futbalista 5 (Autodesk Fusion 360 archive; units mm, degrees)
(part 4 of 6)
sketch "Sketch44" plane through (-7.5563, 42.8538, 0) normal (0.1736, -0.9848, 0) x axis (0.9848, 0.1736, 0)
  line L1 (43.4001, 36.25) -> (43.5001, 36.25)
  line L2 (43.4001, 23.75) -> (43.4001, 36.25)
  line L3 (43.5001, 23.75) -> (43.4001, 23.75)
  line L4 (43.5001, 23.4) -> (43.5001, 23.75)
  line L5 (58.7001, 23.4) -> (43.5001, 23.4)
  line L6 (58.7001, 36.6) -> (58.7001, 23.4)
  line L7 (43.5001, 36.6) -> (58.7001, 36.6)
  line L8 (43.5001, 36.25) -> (43.5001, 36.6)
  line L9 (58.7501, 34.41) -> (58.7501, 35.2)
  line L10 (58.7501, 24.8) -> (58.7501, 25.59)
  line L11 (51.6001, 22.55) -> (49.2001, 22.55)
  line L12 (51.6001, 37.45) -> (49.2001, 37.45)
  line L13 (42.8801, 30.05) -> (42.8801, 32.75)
  line L14 (42.8801, 29.95) -> (42.8801, 27.25)
  line L15 (42.4001, 17.25) -> (42.4001, 6.75)
  line L16 (44.2601, 4.75) -> (47.6601, 4.75)
  line L17 (52.7601, 4.75) -> (56.1601, 4.75)
  line L18 (47.6601, 19.25) -> (44.2601, 19.25)
  line L19 (56.1601, 19.25) -> (52.7601, 19.25)
  line L20 (58.0201, 12.01) -> (58.0201, 17.25)
  line L21 (58.0201, 6.75) -> (58.0201, 11.99)
  line L22 (45.1001, -14.5) -> (45.1001, 1)
  line L23 (45.3001, 1.2) -> (58.4001, 1.2)
  line L24 (58.6001, -4.12) -> (58.6001, -9.18)
  line L25 (58.4001, -14.7) -> (45.3001, -14.7)
  line L26 (45.1001, -14.7) -> (45.3001, -14.7)
  line L27 (45.1001, -14.5) -> (45.1001, -14.7)
  line L28 (58.6001, -14.7) -> (58.4001, -14.7)
  line L29 (58.6001, -9.18) -> (58.6001, -14.7)
  line L30 (58.6001, 1.2) -> (58.6001, -4.12)
  line L31 (58.4001, 1.2) -> (58.6001, 1.2)
  line L32 (45.1001, 1.2) -> (45.3001, 1.2)
  line L33 (45.1001, 1) -> (45.1001, 1.2)
  line L34 (58.0201, 4.75) -> (56.1601, 4.75)
  line L35 (58.0201, 6.75) -> (58.0201, 4.75)
  line L36 (47.6601, 4.75) -> (52.7601, 4.75)
  line L37 (42.4001, 4.75) -> (44.2601, 4.75)
  line L38 (42.4001, 6.75) -> (42.4001, 4.75)
  line L39 (42.4001, 19.25) -> (42.4001, 17.25)
  line L40 (44.2601, 19.25) -> (42.4001, 19.25)
  line L41 (52.7601, 19.25) -> (47.6601, 19.25)
  line L42 (58.0201, 19.25) -> (56.1601, 19.25)
  line L43 (58.0201, 17.25) -> (58.0201, 19.25)
  line L44 (58.0201, 11.99) -> (58.0201, 12.01)
  line L45 (58.7501, 34.41) -> (58.7501, 25.59)
  line L46 (58.7501, 22.55) -> (58.7501, 24.8)
  line L47 (51.6001, 22.55) -> (58.7501, 22.55)
  line L48 (42.8801, 22.55) -> (49.2001, 22.55)
  line L49 (42.8801, 27.25) -> (42.8801, 22.55)
  line L50 (42.8801, 30.05) -> (42.8801, 29.95)
  line L51 (42.8801, 37.45) -> (42.8801, 32.75)
  line L52 (49.2001, 37.45) -> (42.8801, 37.45)
  line L53 (58.7501, 37.45) -> (51.6001, 37.45)
  line L54 (58.7501, 35.2) -> (58.7501, 37.45)
  line L55 (46.1201, 24.45) -> (45.8314, 24.7387)
  line L56 (45.5801, 17.17) -> (45.9601, 17.55)
  line L57 (45.9601, 24.45) -> (45.9601, 17.55)
  line L58 (42.4001, 37.45) -> (42.4001, 19.25)
  line L59 (42.8801, 37.45) -> (42.4001, 37.45)
  line L60 (42.4001, 22.55) -> (42.8801, 22.55)
  line L61 (58.7501, -14.7) -> (58.7501, 22.55)
  line L62 (58.4001, -14.7) -> (58.7501, -14.7)
  line L63 (58.7501, 1.2) -> (58.4001, 1.2)
  line L64 (58.7501, 19.25) -> (58.0201, 19.25)
  line L65 (58.7501, 4.75) -> (58.0201, 4.75)
  line L66 (43.9601, 5.45) -> (43.9601, 5.75)
  line L67 (43.7001, 5.45) -> (43.9601, 5.45)
  line L68 (43.1001, 6.45) -> (43.1001, 6.05)
  line L69 (43.4001, 6.45) -> (43.1001, 6.45)
  line L70 (43.4001, 6.05) -> (43.4001, 6.45)
  line L71 (43.9601, 5.75) -> (43.7001, 5.75)
  line L72 (42.4001, 6.9257) -> (43.488, 5.8379)
  line L73 (44.5758, 4.75) -> (43.488, 5.8379)
  line L74 (43.4001, 19.25) -> (43.4001, 5.9257)
  line L75 (43.4001, 37.45) -> (43.4001, 19.25)
  arc A1 centre (43.7001, 6.05) radius 0.6 clockwise from (43.7001, 5.45) to (43.1001, 6.05)
  arc A2 centre (43.7001, 6.05) radius 0.3 clockwise from (43.7001, 5.75) to (43.4001, 6.05)
  point P42 (45.3001, -14.7)
  point P44 (45.3001, -14.7)
  point P37 (45.1001, -14.5)
  point P46 (45.1001, -14.5)
  point P43 (58.4001, -14.7)
  point P47 (58.4001, -14.7)
  point P40 (58.6001, -9.18)
  point P49 (58.6001, -9.18)
  point P41 (58.6001, -4.12)
  point P50 (58.6001, -4.12)
  point P38 (58.4001, 1.2)
  point P52 (58.4001, 1.2)
  point P39 (45.3001, 1.2)
  point P53 (45.3001, 1.2)
  point P36 (45.1001, 1)
  point P55 (45.1001, 1)
  point P26 (56.1601, 4.75)
  point P56 (56.1601, 4.75)
  point P35 (58.0201, 6.75)
  point P58 (58.0201, 6.75)
  point P27 (52.7601, 4.75)
  point P59 (52.7601, 4.75)
  point P24 (47.6601, 4.75)
  point P60 (47.6601, 4.75)
  point P25 (44.2601, 4.75)
  point P61 (44.2601, 4.75)
  point P22 (42.4001, 6.75)
  point P63 (42.4001, 6.75)
  point P23 (42.4001, 17.25)
  point P64 (42.4001, 17.25)
  point P28 (44.2601, 19.25)
  point P66 (44.2601, 19.25)
  point P29 (47.6601, 19.25)
  point P67 (47.6601, 19.25)
  point P30 (52.7601, 19.25)
  point P68 (52.7601, 19.25)
  point P31 (56.1601, 19.25)
  point P69 (56.1601, 19.25)
  point P32 (58.0201, 17.25)
  point P71 (58.0201, 17.25)
  point P33 (58.0201, 12.01)
  point P72 (58.0201, 12.01)
  point P34 (58.0201, 11.99)
  point P73 (58.0201, 11.99)
  point P12 (58.7501, 25.59)
  point P74 (58.7501, 25.59)
  point P11 (58.7501, 34.41)
  point P75 (58.7501, 34.41)
  point P13 (58.7501, 24.8)
  point P76 (58.7501, 24.8)
  point P15 (51.6001, 22.55)
  point P78 (51.6001, 22.55)
  point P14 (49.2001, 22.55)
  point P79 (49.2001, 22.55)
  point P20 (42.8801, 27.25)
  point P81 (42.8801, 27.25)
  point P21 (42.8801, 29.95)
  point P82 (42.8801, 29.95)
  point P19 (42.8801, 30.05)
  point P83 (42.8801, 30.05)
  point P18 (42.8801, 32.75)
  point P84 (42.8801, 32.75)
  point P16 (49.2001, 37.45)
  point P86 (49.2001, 37.45)
  point P17 (51.6001, 37.45)
  point P87 (51.6001, 37.45)
  point P10 (58.7501, 35.2)
  point P89 (58.7501, 35.2)
  point P92 (45.9601, 17.55)
  point P94 (45.9601, 17.55)
  point P97 (42.4001, 22.55)
  point P99 (58.4001, -14.7)
  point P100 (58.7501, 1.2)
  point P101 (58.7501, 19.25)
  point P102 (58.7501, 4.75)
  point P112 (43.488, 5.8379)
  point P113 (42.4001, 6.9257)
  point P114 (44.5758, 4.75)
  point P115 (43.4001, 5.9257)
  point P116 (43.4001, 19.25)
  point P117 (43.4001, 37.45)
  coincident P42 P44
  perpendicular L22 L26
  coincident P37 P46
  perpendicular L26 L27
  coincident P43 P47
  perpendicular L24 L28
  coincident P40 P49
  perpendicular L28 L29
  coincident P41 P50
  perpendicular L23 L30
  coincident P38 P52
  perpendicular L30 L31
  coincident P39 P53
  perpendicular L22 L32
  coincident P36 P55
  parallel L22 L33
  coincident P26 P56
  perpendicular L21 L34
  coincident P35 P58
  perpendicular L34 L35
  coincident P27 P59
  coincident P24 P60
  coincident P25 P61
  perpendicular L15 L37
  coincident P22 P63
  perpendicular L37 L38
  coincident P23 P64
  perpendicular L18 L39
  coincident P28 P66
  perpendicular L15 L40
  coincident P29 P67
  coincident P30 P68
  coincident P31 P69
  perpendicular L20 L42
  coincident P32 P71
  perpendicular L42 L43
  coincident P33 P72
  coincident P34 P73
  parallel L21 L44
  coincident P12 P74
  coincident P11 P75
  coincident P13 P76
  perpendicular L11 L46
  coincident P15 P78
  perpendicular L46 L47
  coincident P14 P79
  perpendicular L14 L48
  coincident P20 P81
  perpendicular L48 L49
  coincident P21 P82
  coincident P19 P83
  coincident P18 P84
  perpendicular L12 L51
  coincident P16 P86
  perpendicular L13 L52
  coincident P17 P87
  perpendicular L6 L53
  coincident P10 P89
  perpendicular L7 L54
  coincident P92 P94
  perpendicular L5 L57
  perpendicular L52 L58
  perpendicular L51 L59
  coincident L58 P97
  perpendicular L58 L60
  perpendicular L28 L61
  coincident P43 P99
  perpendicular L61 L62
  coincident L61 P100
  perpendicular L61 L63
  coincident L61 P101
  perpendicular L61 L64
  coincident L61 P102
  perpendicular L61 L65
  midpoint A2 P112
  coincident L15 P113
  tangent A2 L72
  coincident L16 P114
  parallel L72 L73
  coincident L72 P115
  coincident L40 P116
  perpendicular L40 L74
  coincident L52 P117
  perpendicular L52 L75
extrude "Extrude66" cut sketch "Sketch44" profile of L1 L2 L3 L4 L5 L6 L7 L8 L9 L10 L11 L12 L16 L17 L18 L19 L20 L21 L22 L23 L24 L25 L26 L27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 against normal blind 30
sketch "Sketch45" plane through (0, 0, 39) normal (0, 0, 1) x axis (-1, 0, 0)
  line L1 (-49.8417, -64.0123) -> (-63.5599, 13.7875)
  line L2 (-48.266, -63.7344) -> (-49.8417, -64.0123)
  line L3 (-61.9842, 14.0654) -> (-48.266, -63.7344)
  line L4 (-63.5599, 13.7875) -> (-61.9842, 14.0654)
  line L5 (-48.266, -63.7344) -> (-47.7451, -66.6889)
  line L6 (-49.8417, -64.0123) -> (-48.266, -63.7344)
  line L7 (-49.3208, -66.9667) -> (-49.8417, -64.0123)
  line L8 (-47.7451, -66.6889) -> (-49.3208, -66.9667)
extrude "Extrude67" cut sketch "Sketch45" profile of L2 L5 L6 L7 L8 against normal blind 61.25
extrude "Extrude68" cut of existing geometry blind -5
offset_faces "OffsetFaces22" distance -0.2
sketch "Sketch46" plane through (0, 0, -22.25) normal (0, 0, -1) x axis (1, 0, 0)
  line L1 (-34.4019, -65.5859) -> (-35.4437, -67.3902)
  line L2 (-31.3708, -67.3359) -> (-34.4019, -65.5859)
  line L3 (-34.3708, -72.532) -> (-31.3708, -67.3359)
  line L4 (-37.4019, -70.782) -> (-34.3708, -72.532)
  line L5 (-36.3602, -68.9777) -> (-37.4019, -70.782)
  line L6 (-40.866, -68.782) -> (-39.8243, -66.9777)
  line L7 (-45.6292, -66.032) -> (-40.866, -68.782)
  line L8 (-42.6292, -60.8359) -> (-45.6292, -66.032)
  line L9 (-37.866, -63.5859) -> (-42.6292, -60.8359)
  line L10 (-38.9078, -65.3902) -> (-37.866, -63.5859)
  line L11 (42.5981, 67.782) -> (41.5563, 65.9777)
  line L12 (45.6292, 66.032) -> (42.5981, 67.782)
  line L13 (42.6292, 60.8359) -> (45.6292, 66.032)
  line L14 (39.5981, 62.5859) -> (42.6292, 60.8359)
  line L15 (40.6398, 64.3902) -> (39.5981, 62.5859)
  line L16 (36.134, 64.5859) -> (37.1757, 66.3902)
  line L17 (31.3708, 67.3359) -> (36.134, 64.5859)
  line L18 (34.3708, 72.532) -> (31.3708, 67.3359)
  line L19 (39.134, 69.782) -> (34.3708, 72.532)
  line L20 (38.0922, 67.9777) -> (39.134, 69.782)
  line L21 (-39.5981, 62.5859) -> (-40.6398, 64.3902)
  line L22 (-42.6292, 60.8359) -> (-39.5981, 62.5859)
  line L23 (-45.6292, 66.032) -> (-42.6292, 60.8359)
  line L24 (-42.5981, 67.782) -> (-45.6292, 66.032)
  line L25 (-41.5563, 65.9777) -> (-42.5981, 67.782)
  line L26 (-39.134, 69.782) -> (-38.0922, 67.9777)
  line L27 (-34.3708, 72.532) -> (-39.134, 69.782)
  line L28 (-31.3708, 67.3359) -> (-34.3708, 72.532)
  line L29 (-36.134, 64.5859) -> (-31.3708, 67.3359)
  line L30 (-37.1757, 66.3902) -> (-36.134, 64.5859)
  line L31 (37.4019, -70.782) -> (36.3602, -68.9777)
  line L32 (34.3708, -72.532) -> (37.4019, -70.782)
  line L33 (31.3708, -67.3359) -> (34.3708, -72.532)
  line L34 (34.4019, -65.5859) -> (31.3708, -67.3359)
  line L35 (35.4437, -67.3902) -> (34.4019, -65.5859)
  line L36 (37.866, -63.5859) -> (38.9078, -65.3902)
  line L37 (42.6292, -60.8359) -> (37.866, -63.5859)
  line L38 (45.6292, -66.032) -> (42.6292, -60.8359)
  line L39 (40.866, -68.782) -> (45.6292, -66.032)
  line L40 (39.8243, -66.9777) -> (40.866, -68.782)
  line L41 (80, -1) -> (77.9165, -1)
  line L42 (80, -6.5) -> (80, -1)
  line L43 (74, -6.5) -> (80, -6.5)
  line L44 (74, -1) -> (74, -6.5)
  line L45 (76.0835, -1) -> (74, -1)
  line L46 (74, 3) -> (76.0835, 3)
  line L47 (74, 6.5) -> (74, 3)
  line L48 (80, 6.5) -> (74, 6.5)
  line L49 (80, 3) -> (80, 6.5)
  line L50 (77.9165, 3) -> (80, 3)
  line L51 (-74, -1) -> (-76.0835, -1)
  line L52 (-74, -6.5) -> (-74, -1)
  line L53 (-80, -6.5) -> (-74, -6.5)
  line L54 (-80, -1) -> (-80, -6.5)
  line L55 (-77.9165, -1) -> (-80, -1)
  line L56 (-80, 3) -> (-77.9165, 3)
  line L57 (-80, 6.5) -> (-80, 3)
  line L58 (-74, 6.5) -> (-80, 6.5)
  line L59 (-74, 3) -> (-74, 6.5)
  line L60 (-76.0835, 3) -> (-74, 3)
  line L61 (20.0255, 60.7) -> (20.0255, 82.8712)
  line L62 (-20.0255, 60.7) -> (20.0255, 60.7)
  line L63 (-20.0255, 82.8712) -> (-20.0255, 60.7)
  line L64 (-41.4358, 58.564) -> (-55.2616, 66.5463)
  line L65 (-71.4358, 6.6024) -> (-41.4358, 58.564)
  line L66 (-85.2616, 14.5848) -> (-71.4358, 6.6024)
  line L67 (-30, -65.1664) -> (-30, -81.1311)
  line L68 (30, -65.1664) -> (-30, -65.1664)
  line L69 (30, -81.1311) -> (30, -65.1664)
  line L70 (71.4358, 6.6024) -> (85.2616, 14.5848)
  line L71 (41.4358, 58.564) -> (71.4358, 6.6024)
  line L72 (55.2616, 66.5463) -> (41.4358, 58.564)
  curve K1 (-4.8614, 50.6873) -> (-8.9488, 53.7854)
  curve K2 (-6.0976, 56.6484) -> (-3.0014, 52.525)
  circle C1 centre (-47, -60.7321) radius 3.2
  circle C2 centre (76.0955, -10.3372) radius 3.2
  circle C3 centre (29.0955, 71.0692) radius 3.2
  circle C4 centre (-34.6756, 10.8401) radius 3.4
  circle C5 centre (-38.6768, 31.5099) radius 3.4
  circle C6 centre (38.6768, 31.5099) radius 3.4
  circle C7 centre (34.6756, 10.8401) radius 3.4
  circle C8 centre (7.95, -35.45) radius 3.4
  circle C9 centre (-7.95, -49.25) radius 3.4
  arc A1 centre (-37.634, -67.184) radius 2.2 clockwise from (-38.9078, -65.3902) to (-35.4437, -67.3902)
  arc A2 centre (-37.634, -67.184) radius 2.2 clockwise from (-36.3602, -68.9777) to (-39.8243, -66.9777)
  arc A3 centre (39.366, 66.184) radius 2.2 clockwise from (38.0922, 67.9777) to (41.5563, 65.9777)
  arc A4 centre (39.366, 66.184) radius 2.2 clockwise from (40.6398, 64.3902) to (37.1757, 66.3902)
  arc A5 centre (-39.366, 66.184) radius 2.2 clockwise from (-37.1757, 66.3902) to (-40.6398, 64.3902)
  arc A6 centre (-39.366, 66.184) radius 2.2 clockwise from (-41.5563, 65.9777) to (-38.0922, 67.9777)
  arc A7 centre (37.634, -67.184) radius 2.2 clockwise from (39.8243, -66.9777) to (36.3602, -68.9777)
  arc A8 centre (37.634, -67.184) radius 2.2 clockwise from (35.4437, -67.3902) to (38.9078, -65.3902)
  arc A9 centre (77, 1) radius 2.2 clockwise from (77.9165, 3) to (77.9165, -1)
  arc A10 centre (77, 1) radius 2.2 clockwise from (76.0835, -1) to (76.0835, 3)
  arc A11 centre (-77, 1) radius 2.2 clockwise from (-76.0835, 3) to (-76.0835, -1)
  arc A12 centre (-77, 1) radius 2.2 clockwise from (-77.9165, -1) to (-77.9165, 3)
  arc A13 centre (0, 128.856) radius 50.156 clockwise from (-20.0255, 82.8712) to (-21.8303, 83.7)
  arc A14 centre (0, 0) radius 86.5 clockwise from (-55.2616, 66.5463) to (-21.8303, 83.7)
  arc A15 centre (0, 0) radius 86.5 clockwise from (-30, -81.1311) to (-85.2616, 14.5848)
  arc A16 centre (0, 0) radius 86.5 clockwise from (85.2616, 14.5848) to (30, -81.1311)
  arc A17 centre (0, 0) radius 86.5 clockwise from (21.8303, 83.7) to (55.2616, 66.5463)
  arc A18 centre (0, 128.856) radius 50.156 clockwise from (21.8303, 83.7) to (20.0255, 82.8712)
  circle C10 centre (-7.95, -35.45) radius 3.4
  circle C11 centre (7.95, -49.25) radius 3.4
  circle C12 centre (46.6268, 17.7401) radius 3.4
  circle C13 centre (26.7256, 24.6099) radius 3.4
  arc A19 centre (-6, 53.7) radius 3.2206 clockwise from (-3.0014, 52.525) to (-4.8614, 50.6873)
  arc A20 centre (-6, 53.7) radius 2.95 clockwise from (-8.9488, 53.7854) to (-6.0976, 56.6484)
  circle C14 centre (-46.6268, 17.7401) radius 3.4
  circle C15 centre (-26.7256, 24.6099) radius 3.4
  circle C16 centre (-29.0955, 71.0692) radius 3.2
  circle C17 centre (47, -60.7321) radius 3.2
  circle C18 centre (-76.0955, -10.3372) radius 3.2
extrude "Extrude70" add sketch "Sketch46" profile of C17 against normal blind 5
sketch "Sketch47" plane through (0, 0, 32.75) normal (0, 0, 1) x axis (-1, 0, 0)
  line L1 (-53.6322, -52.2827) -> (-55.1347, -54.8851)
  line L2 (-55.1347, -49.2327) -> (-53.6322, -51.8351)
  line L3 (-58.5273, -49.0089) -> (-55.5223, -49.0089)
  line L4 (-60.4175, -51.8351) -> (-58.915, -49.2327)
  line L5 (-58.915, -54.8851) -> (-60.4175, -52.2827)
  line L6 (-55.5223, -55.1089) -> (-58.5273, -55.1089)
  arc A1 centre (-57.0248, -52.0589) radius 3.4 clockwise from (-53.6322, -51.8351) to (-53.6322, -52.2827)
  arc A2 centre (-57.0248, -52.0589) radius 3.4 clockwise from (-55.5223, -49.0089) to (-55.1347, -49.2327)
  arc A3 centre (-57.0248, -52.0589) radius 3.4 clockwise from (-58.915, -49.2327) to (-58.5273, -49.0089)
  arc A4 centre (-57.0248, -52.0589) radius 3.4 clockwise from (-60.4175, -52.2827) to (-60.4175, -51.8351)
  arc A5 centre (-57.0248, -52.0589) radius 3.4 clockwise from (-58.5273, -55.1089) to (-58.915, -54.8851)
  arc A6 centre (-57.0248, -52.0589) radius 3.4 clockwise from (-55.1347, -54.8851) to (-55.5223, -55.1089)
  circle C1 centre (-57.0248, -52.0589) radius 1.7
  concentric A1 C1
  dimension "d370" diameter C1 = 3.4
extrude "Extrude71" cut sketch "Sketch47" profile of C1 against normal blind 55
chamfer "Chamfer6" distance 1.5
sketch "Sketch48" plane through (0, 0, 34.75) normal (0, 0, 1) x axis (-1, 0, 0)
  line L1 (-49.483, -67.1984) -> (-48.055, -66.9466)
  line L2 (-49.9034, -64.8143) -> (-49.483, -67.1984)
  line L3 (-48.055, -66.9466) -> (-47.6146, -69.4441)
  line L4 (-32, -74.955) -> (-32, -78.2065)
  line L5 (-83.7288, 11.3904) -> (-80.9129, 9.7647)
  line L6 (45.4975, -57.6821) -> (48.5025, -57.6821)
  line L7 (43.6074, -60.5083) -> (45.1099, -57.9059)
  line L8 (45.1099, -63.5583) -> (43.6074, -60.9559)
  line L9 (48.5025, -63.7821) -> (45.4975, -63.7821)
  line L10 (50.3926, -60.9559) -> (48.8901, -63.5583)
  line L11 (48.8901, -57.9059) -> (50.3926, -60.5083)
  line L12 (74.593, -7.2872) -> (77.598, -7.2872)
  line L13 (72.7029, -10.1134) -> (74.2054, -7.511)
  line L14 (74.2054, -13.1634) -> (72.7029, -10.561)
  line L15 (77.598, -13.3872) -> (74.593, -13.3872)
  line L16 (79.4881, -10.561) -> (77.9856, -13.1634)
  line L17 (77.9856, -7.511) -> (79.4881, -10.1134)
  line L18 (27.2054, 68.243) -> (25.7029, 70.8454)
  line L19 (30.598, 68.0192) -> (27.593, 68.0192)
  line L20 (32.4881, 70.8454) -> (30.9856, 68.243)
  line L21 (30.9856, 73.8954) -> (32.4881, 71.293)
  line L22 (27.593, 74.1192) -> (30.598, 74.1192)
  line L23 (25.7029, 71.293) -> (27.2054, 73.8954)
  line L24 (-30.9856, 68.243) -> (-32.4881, 70.8454)
  line L25 (-27.593, 68.0192) -> (-30.598, 68.0192)
  line L26 (-25.7029, 70.8454) -> (-27.2054, 68.243)
  line L27 (-27.2054, 73.8954) -> (-25.7029, 71.293)
  line L28 (-30.598, 74.1192) -> (-27.593, 74.1192)
  line L29 (-32.4881, 71.293) -> (-30.9856, 73.8954)
  line L30 (-72.7029, -10.561) -> (-74.2054, -13.1634)
  line L31 (-74.2054, -7.511) -> (-72.7029, -10.1134)
  line L32 (-77.598, -7.2872) -> (-74.593, -7.2872)
  line L33 (-79.4881, -10.1134) -> (-77.9856, -7.511)
  line L34 (-77.9856, -13.1634) -> (-79.4881, -10.561)
  line L35 (-74.593, -13.3872) -> (-77.598, -13.3872)
  line L36 (-53.6322, -52.2827) -> (-55.1347, -54.8851)
  line L37 (-55.1347, -49.2327) -> (-53.6322, -51.8351)
  line L38 (-58.5273, -49.0089) -> (-55.5223, -49.0089)
  line L39 (-60.4175, -51.8351) -> (-58.915, -49.2327)
  line L40 (-58.915, -54.8851) -> (-60.4175, -52.2827)
  line L41 (-55.5223, -55.1089) -> (-58.5273, -55.1089)
  line L42 (23, -21.1848) -> (23, 13.8152)
  line L43 (-23, 13.8152) -> (-23, -21.1848)
  line L44 (-12.1244, -61.1848) -> (12.1244, -61.1848)
  line L45 (23, -61.1848) -> (23, -21.1848)
  line L46 (12.1244, -61.1848) -> (23, -61.1848)
  line L47 (-23, -61.1848) -> (-12.1244, -61.1848)
  line L48 (-23, -21.1848) -> (-23, -61.1848)
  line L49 (23, 13.8152) -> (-23, 13.8152)
  line L50 (14, 20.6152) -> (14, 17.8152)
  line L51 (-14, 20.6152) -> (14, 20.6152)
  line L52 (-14, 17.8152) -> (-14, 20.6152)
  line L53 (14, 17.8152) -> (-14, 17.8152)
  line L54 (14, 50) -> (14, 20.6152)
  line L55 (-14, 50) -> (14, 50)
  line L56 (-14, 20.6152) -> (-14, 50)
  line L57 (-60.0098, 2.8681) -> (-61.1108, 9.1118)
  line L58 (-57.9524, 1.9108) -> (-58.5038, 1.8136)
  line L59 (-57.9988, 9.6605) -> (-56.8978, 3.4168)
  line L60 (-60.0563, 10.6178) -> (-59.5048, 10.715)
  line L61 (-60.8153, 9.1639) -> (-59.7144, 2.9202)
  line L62 (-59.4527, 10.4196) -> (-60.0042, 10.3223)
  line L63 (-57.1933, 3.3647) -> (-58.2942, 9.6084)
  line L64 (-58.5559, 2.109) -> (-58.0044, 2.2063)
  line L65 (-58.2169, -6.4364) -> (-57.8704, -8.4016)
  line L66 (-57.605, -5.453) -> (-58.1625, -6.2057)
  line L67 (-56.1158, -5.1069) -> (-57.416, -5.3361)
  line L68 (-54.7959, -10.8651) -> (-55.7683, -5.3502)
  line L69 (-56.3394, -11.4419) -> (-55.0392, -11.2127)
  line L70 (-57.3383, -10.8801) -> (-56.5569, -11.3967)
  line L71 (-57.8148, -8.7167) -> (-57.4683, -10.6819)
  line L72 (-57.9625, -8.7428) -> (-57.8148, -8.7167)
  line L73 (-57.616, -10.708) -> (-57.9625, -8.7428)
  line L74 (-56.6396, -11.5219) -> (-57.421, -11.0052)
  line L75 (-55.0132, -11.3604) -> (-56.3133, -11.5896)
  line L76 (-55.6206, -5.3242) -> (-54.6482, -10.8391)
  line L77 (-57.442, -5.1884) -> (-56.1419, -4.9591)
  line L78 (-58.2831, -6.1165) -> (-57.7255, -5.3637)
  line L79 (-58.0181, -8.4276) -> (-58.3646, -6.4624)
  line L80 (-57.8704, -8.4016) -> (-58.0181, -8.4276)
  line L81 (-55.8726, -19.7313) -> (-55.5261, -21.6965)
  line L82 (-55.2607, -18.7479) -> (-55.8183, -19.5006)
  line L83 (-53.7716, -18.4018) -> (-55.0717, -18.631)
  line L84 (-52.4516, -24.16) -> (-53.4241, -18.6451)
  line L85 (-53.9951, -24.7368) -> (-52.695, -24.5076)
  line L86 (-54.9941, -24.175) -> (-54.2127, -24.6916)
  line L87 (-55.4706, -22.0116) -> (-55.124, -23.9768)
  line L88 (-55.6183, -22.0377) -> (-55.4706, -22.0116)
  line L89 (-55.2718, -24.0029) -> (-55.6183, -22.0377)
  line L90 (-54.2954, -24.8168) -> (-55.0768, -24.3001)
  line L91 (-52.6689, -24.6553) -> (-53.9691, -24.8846)
  line L92 (-53.2763, -18.6191) -> (-52.3039, -24.134)
  line L93 (-55.0978, -18.4833) -> (-53.7976, -18.2541)
  line L94 (-55.9388, -19.4114) -> (-55.3812, -18.6586)
  line L95 (-55.6738, -21.7225) -> (-56.0204, -19.7574)
  line L96 (-55.5261, -21.6965) -> (-55.6738, -21.7225)
  line L97 (-55.6183, -22.0377) -> (-55.6738, -21.7225)
  line L98 (-58.0181, -8.4276) -> (-57.9625, -8.7428)
  line L99 (-47.2673, -71.4137) -> (-47.6146, -69.4441)
  line L100 (-30.5256, -68.4617) -> (-47.2673, -71.4137)
  line L101 (-33.9986, -48.7656) -> (-30.5256, -68.4617)
  line L102 (-44.4868, -50.6149) -> (-47.2193, -35.1179)
  line L103 (-33.9986, -48.7656) -> (-44.4868, -50.6149)
  line L104 (-52.1683, -51.9694) -> (-49.9034, -64.8143)
  line L105 (-44.4868, -50.6149) -> (-52.1683, -51.9694)
  line L106 (-64.3237, 16.9672) -> (-52.1683, -51.9694)
  line L107 (-56.6422, 18.3216) -> (-47.2193, -35.1179)
  line L108 (-64.3237, 16.9672) -> (-56.6422, 18.3216)
  line L109 (-47.2673, -71.4137) -> (-47.0623, -72.5768)
  line L110 (-28.1769, -81.7821) -> (-30.5256, -68.4617)
  line L111 (-29.9937, -78.6767) -> (-30.4818, -75.9085)
  arc A1 centre (0, 0) radius 81.8 clockwise from (-49.9034, -64.8143) to (-30.4818, -75.9085)
  arc A2 centre (0, 0) radius 84.2 clockwise from (-47.6146, -69.4441) to (-29.9937, -78.6767)
  arc A3 centre (0, 0) radius 81.5 clockwise from (-32, -74.955) to (-80.9129, 9.7647)
  arc A4 centre (0, 0) radius 84.5 clockwise from (-32, -78.2065) to (-83.7288, 11.3904)
  circle C1 centre (0, 0) radius 81.5
  arc A5 centre (0, 0) radius 86.5 clockwise from (-30, -81.1311) to (-85.2616, 14.5848)
  circle C2 centre (0, 0) radius 86.5
  arc A6 centre (47, -60.7321) radius 3.4 clockwise from (45.1099, -57.9059) to (45.4975, -57.6821)
  arc A7 centre (47, -60.7321) radius 3.4 clockwise from (43.6074, -60.9559) to (43.6074, -60.5083)
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  point P104 (23, -21.1848)
  point P109 (23, -21.1848)
  point P107 (12.1244, -61.1848)
  point P111 (12.1244, -61.1848)
  point P108 (-12.1244, -61.1848)
  point P112 (-12.1244, -61.1848)
  point P105 (-23, -21.1848)
  point P114 (-23, -21.1848)
  point P106 (-23, 13.8152)
  point P115 (-23, 13.8152)
  point P103 (23, 13.8152)
  point P116 (23, 13.8152)
  point P118 (14, 20.6152)
  point P121 (14, 20.6152)
  point P119 (-14, 20.6152)
  point P124 (-14, 20.6152)
  point P212 (-55.6738, -21.7225)
  point P214 (-55.6738, -21.7225)
  point P199 (-55.6183, -22.0377)
  point P215 (-55.6183, -22.0377)
  point P165 (-57.9625, -8.7428)
  point P216 (-57.9625, -8.7428)
  point P178 (-58.0181, -8.4276)
  point P217 (-58.0181, -8.4276)
  point P8 (-47.6146, -69.4441)
  point P219 (-47.6146, -69.4441)
  point P4 (-49.9034, -64.8143)
  point P225 (-49.9034, -64.8143)
  point P229 (-47.0623, -72.5768)
  point P230 (-28.1769, -81.7821)
  point P220 (-47.2673, -71.4137)
  point P221 (-30.5256, -68.4617)
  point P222 (-33.9986, -48.7656)
  point P226 (-52.1683, -51.9694)
  point P227 (-64.3237, 16.9672)
  coincident P104 P109
  perpendicular L44 L45
  coincident P107 P111
  perpendicular L45 L46
  coincident P108 P112
  perpendicular L43 L47
  coincident P105 P114
  perpendicular L47 L48
  coincident P106 P115
  coincident P103 P116
  coincident P118 P121
  perpendicular L53 L54
  perpendicular L52 L55
  coincident P119 P124
  perpendicular L51 L56
  coincident P212 P214
  coincident P199 P215
  coincident P165 P216
  coincident P178 P217
  coincident P8 P219
  parallel L3 L99
  perpendicular L99 L100
  perpendicular L100 L101
  coincident P4 P225
  perpendicular L103 L104
  perpendicular L102 L105
  perpendicular L105 L106
  perpendicular L106 L108
  coincident C2 P229
  coincident C2 P230
  perpendicular L100 L110
  dimension "d374" diameter = 3.4
  dimension "d375" diameter = 3.4
  dimension "d376" diameter = 3.4
  dimension "d384" distance P219 P220 = 2
  dimension "d385" distance P220 P221 = 17
  dimension "d386" distance P221 P222 = 20
  dimension "d387" distance P226 P227 = 70
  dimension "d378" C-Pattern1-Angle = 360
extrude "Extrude72" new body sketch "Sketch48" along normal blind 6.65 and along normal blind 4.55
offset_faces "OffsetFaces23" distance -0.2
extrude "Extrude73" add sketch "Sketch48" along normal blind 4.55 and along normal blind 2
extrude "Extrude74" add sketch "Sketch48" along normal blind 6.65
extrude "Extrude75" add sketch "Sketch48" against normal blind 2
extrude "Extrude77" cut sketch "Sketch48" along normal blind 5 and against normal blind 2
offset_faces "OffsetFaces24" distance -0.2
position "Position46"
sketch "Sketch49" plane through (0, -11.6094, -4.1835) normal (0, -0.9397, -0.342) x axis (1, 0, 0)
  line L1 (7, 25.7493) -> (-7, 25.7493)
  line L2 (7, 29.2493) -> (7, 25.7493)
  line L3 (14, 29.2493) -> (7, 29.2493)
  line L4 (14, 56.2493) -> (14, 29.2493)
  line L5 (-14, 56.2493) -> (14, 56.2493)
  line L6 (-14, 29.2493) -> (-14, 56.2493)
  line L7 (-7, 29.2493) -> (-14, 29.2493)
  line L8 (-7, 25.7493) -> (-7, 29.2493)
  circle C1 centre (-10.5, 45.2493) radius 1.1
  circle C2 centre (10.5, 45.2493) radius 1.1
  circle C3 centre (-10.5, 32.7493) radius 1.1
  circle C4 centre (10.5, 32.7493) radius 1.1
  circle C5 centre (0, 46.7493) radius 5
  circle C6 centre (0, 46.7493) radius 15
  concentric C5 C6
  dimension "d397" diameter C6 = 30
sketch "Sketch50" plane through (7.2, 0, 0) normal (-1, 0, 0) x axis (0, -1, 0)
  line L1 (13.8152, 15.5649) -> (13.8152, 14.6416)
  line L2 (13.8152, 21.1416) -> (13.8152, 15.5649)
  line L3 (20.8152, 14.6416) -> (20.8152, 21.1416)
  line L4 (13.8152, 14.6416) -> (20.8152, 14.6416)
  circle C1 centre (17.3152, 21.1416) radius 1.7
  arc A1 centre (17.3152, 21.1416) radius 3.5 clockwise from (20.8152, 21.1416) to (13.8152, 21.1416)
  arc A2 centre (17.3152, 21.1416) radius 3.5 clockwise from (13.8152, 21.1416) to (20.8152, 21.1416)
  arc A3 centre (17.3152, 21.1416) radius 3.5 clockwise from (13.8152, 21.1416) to (20.8152, 21.1416)
  circle C2 centre (17.3152, 21.1416) radius 1.7
extrude "Extrude78" add sketch "Sketch50" profile of A1 L1 L2 L3 L4 along normal blind 21.2
position "Position48"
position "Position49"
sketch "Sketch51" plane through (0, 0, -17.25) normal (0, 0, 1) x axis (-1, 0, 0)
  line L1 (-13.35, -60.5) -> (13.35, -60.5)
  line L2 (-13.35, -30.3) -> (-13.35, -60.5)
  line L3 (10.15, -27.1) -> (-10.15, -27.1)
  line L4 (13.35, -60.5) -> (13.35, -30.3)
  line L5 (-23, 32.2) -> (-23, 28.6943)
  line L6 (-13.35, -7.7076) -> (-23, -2.1362)
  line L7 (-13.35, -21.1848) -> (-13.35, -7.7076)
  line L8 (-19.5656, 26.7114) -> (0, 15.4153)
  line L9 (-28.5443, 4.7598) -> (-18.3943, 22.3402)
  line L10 (-57.5696, 17.8226) -> (-32.9156, 3.5886)
  line L11 (-56.1424, 9.7285) -> (-57.5696, 17.8226)
  line L12 (-60.8695, 8.895) -> (-56.1424, 9.7285)
  line L13 (-62.6555, 19.0241) -> (-60.8695, 8.895)
  line L14 (-59.3277, 19.6109) -> (-62.6555, 19.0241)
  line L15 (-59.5626, 19.2042) -> (-59.3277, 19.6109)
  line L16 (-58.9695, 18.8618) -> (-59.5626, 19.2042)
  line L17 (-45.7195, 41.8114) -> (-58.9695, 18.8618)
  line L18 (-23, 28.6943) -> (-45.7195, 41.8114)
  line L19 (-11.5, 32.2) -> (-23, 32.2)
  line L20 (-11.5, 59.2) -> (-11.5, 32.2)
  line L21 (-5.5, 59.2) -> (-11.5, 59.2)
  line L22 (-5.5, 58.2) -> (-5.5, 59.2)
  line L23 (5.5, 58.2) -> (-5.5, 58.2)
  line L24 (5.5, 59.2) -> (5.5, 58.2)
  line L25 (11.5, 59.2) -> (5.5, 59.2)
  line L26 (11.5, 32.2) -> (11.5, 59.2)
  line L27 (23, 32.2) -> (11.5, 32.2)
  line L28 (23, 28.6943) -> (23, 32.2)
  line L29 (45.7195, 41.8114) -> (23, 28.6943)
  line L30 (59.0695, 18.6886) -> (45.7195, 41.8114)
  line L31 (32.9156, 3.5886) -> (59.0695, 18.6886)
  line L32 (18.3943, 22.3402) -> (28.5443, 4.7598)
  line L33 (0, 15.4153) -> (19.5656, 26.7114)
  line L34 (-80.9129, 9.7647) -> (-83.7288, 11.3904)
  line L35 (-32, -78.2065) -> (-32, -74.955)
  line L36 (-22.0255, 78.4674) -> (-22.0255, 81.579)
  line L37 (-51.7288, 66.816) -> (-48.9129, 65.1903)
  line L38 (34.3708, 72.532) -> (31.3708, 67.3359)
  line L39 (45.6292, 66.032) -> (34.3708, 72.532)
  line L40 (42.6292, 60.8359) -> (45.6292, 66.032)
  line L41 (31.3708, 67.3359) -> (42.6292, 60.8359)
  line L42 (48.9129, 65.1903) -> (51.7288, 66.816)
  line L43 (22.0255, 81.579) -> (22.0255, 78.4674)
  line L44 (-74, 6.5) -> (-80, 6.5)
  line L45 (-74, -6.5) -> (-74, 6.5)
  line L46 (-80, -6.5) -> (-74, -6.5)
  line L47 (-80, 6.5) -> (-80, -6.5)
  line L48 (45.6292, -66.032) -> (42.6292, -60.8359)
  line L49 (34.3708, -72.532) -> (45.6292, -66.032)
  line L50 (31.3708, -67.3359) -> (34.3708, -72.532)
  line L51 (42.6292, -60.8359) -> (31.3708, -67.3359)
  line L52 (74, -6.5) -> (80, -6.5)
  line L53 (74, 6.5) -> (74, -6.5)
  line L54 (80, 6.5) -> (74, 6.5)
  line L55 (80, -6.5) -> (80, 6.5)
  line L56 (-45.6292, -66.032) -> (-34.3708, -72.532)
  line L57 (-42.6292, -60.8359) -> (-45.6292, -66.032)
  line L58 (-31.3708, -67.3359) -> (-42.6292, -60.8359)
  line L59 (-34.3708, -72.532) -> (-31.3708, -67.3359)
  line L60 (-34.3708, 72.532) -> (-45.6292, 66.032)
  line L61 (-31.3708, 67.3359) -> (-34.3708, 72.532)
  line L62 (-42.6292, 60.8359) -> (-31.3708, 67.3359)
  line L63 (-45.6292, 66.032) -> (-42.6292, 60.8359)
  line L64 (-52.7675, -48.5711) -> (-54.5535, -38.442)
  line L65 (-54.4417, -48.8663) -> (-52.7675, -48.5711)
  line L66 (-56.2277, -38.7372) -> (-54.4417, -48.8663)
  line L67 (-54.5535, -38.442) -> (-56.2277, -38.7372)
  line L68 (-46.0708, -47.3903) -> (-47.8568, -37.2612)
  line L69 (-50.7979, -48.2238) -> (-46.0708, -47.3903)
  line L70 (-52.5839, -38.0947) -> (-50.7979, -48.2238)
  line L71 (-47.8568, -37.2612) -> (-52.5839, -38.0947)
  line L72 (59.151, -17.8417) -> (59.151, -6.8417)
  line L73 (53.851, -17.8417) -> (59.151, -17.8417)
  line L74 (53.851, -6.8417) -> (53.851, -17.8417)
  line L75 (59.151, -6.8417) -> (53.851, -6.8417)
  line L76 (59.151, -56.0662) -> (59.151, -46.8417)
  line L77 (83.7288, 11.3904) -> (80.9129, 9.7647)
  line L78 (32, -74.955) -> (32, -78.2065)
  line L79 (53.851, -57.8417) -> (57.4159, -57.8417)
  line L80 (53.851, -46.8417) -> (53.851, -57.8417)
  line L81 (59.151, -46.8417) -> (53.851, -46.8417)
  line L82 (-64.5876, 18.4639) -> (-41.4358, 58.564)
  line L83 (-62.8391, 8.5477) -> (-64.5876, 18.4639)
  line L84 (-64.5133, 8.2525) -> (-62.8391, 8.5477)
  line L85 (-65.9099, 16.1735) -> (-64.5133, 8.2525)
  line L86 (-71.4358, 6.6024) -> (-65.9099, 16.1735)
  line L87 (-85.2616, 14.5848) -> (-71.4358, 6.6024)
  line L88 (-30, -65.1664) -> (-30, -81.1311)
  line L89 (30, -65.1664) -> (-30, -65.1664)
  line L90 (30, -81.1311) -> (30, -65.1664)
  line L91 (71.4358, 6.6024) -> (85.2616, 14.5848)
  line L92 (41.4358, 58.564) -> (71.4358, 6.6024)
  line L93 (55.2616, 66.5463) -> (41.4358, 58.564)
  line L94 (20.0255, 60.7) -> (20.0255, 82.8712)
  line L95 (-20.0255, 60.7) -> (20.0255, 60.7)
  line L96 (-20.0255, 82.8712) -> (-20.0255, 60.7)
  line L97 (-41.4358, 58.564) -> (-55.2616, 66.5463)
  line L98 (13.35, -7.7076) -> (13.35, -21.1848)
  line L99 (23, -2.1362) -> (13.35, -7.7076)
  line L100 (23, -21.1848) -> (23, -2.1362)
  line L101 (41.4358, 58.564) -> (23, 32.2)
  line L102 (47.0288, 66.5623) -> (41.4358, 58.564)
  line L103 (20.5595, 32.2) -> (21.361, 33.3461)
  line L104 (45.3813, 67.6963) -> (21.361, 33.3461)
  line L105 (47.1008, 70.1553) -> (45.3813, 67.6963)
  line L106 (-45.3813, 67.6963) -> (-21.361, 33.3461)
  line L107 (-41.4358, 58.564) -> (-23, 32.2)
  line L108 (-47.0288, 66.5623) -> (-41.4358, 58.564)
  line L109 (-47.1008, 70.1553) -> (-45.3813, 67.6963)
  line L110 (-20.5595, 32.2) -> (-21.361, 33.3461)
  line L111 (48.748, 69.0209) -> (47.0288, 66.5623)
  line L112 (46.2411, 68.9258) -> (47.8884, 67.7916)
  line L113 (-48.748, 69.0209) -> (-47.0288, 66.5623)
  line L114 (-46.2411, 68.9258) -> (-47.8884, 67.7916)
  line L115 (13.35, -21.1848) -> (23, -21.1848)
  line L116 (-23, -21.1848) -> (-13.35, -21.1848)
  line L117 (-23, -2.1362) -> (-23, -21.1848)
  line L118 (22.151, -57.8417) -> (22.151, -46.8417)
  line L119 (16.151, -57.8417) -> (22.151, -57.8417)
  line L120 (16.151, -46.8417) -> (16.151, -57.8417)
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  point P40 (23, 32.2)
  point P140 (23, 32.2)
  point P126 (41.4358, 58.564)
  point P141 (41.4358, 58.564)
  point P144 (20.5595, 32.2)
  point P155 (47.8884, 67.7916)
  point P156 (46.2411, 68.9258)
  point P158 (-47.8884, 67.7916)
  point P159 (-46.2411, 68.9258)
  point P143 (21.361, 33.3461)
  coincident P40 P140
  coincident P126 P141
  parallel L101 L102
  coincident L27 P144
  parallel L104 L105
  parallel L102 L111
  midpoint L111 P155
  midpoint L105 P156
  parallel L109 L113
  midpoint L113 P158
  midpoint L109 P159
  dimension "d408" distance P140 P143 = 2
extrude "Extrude79" add sketch "Sketch51" along normal blind 52
sketch "Sketch52" plane through (0, 0, 34.75) normal (0, 0, 1) x axis (-1, 0, 0)
  line L1 (-48.055, -66.9466) -> (-47.6146, -69.4441)
  line L2 (-49.483, -67.1984) -> (-48.055, -66.9466)
  line L3 (-49.9034, -64.8143) -> (-49.483, -67.1984)
  line L4 (-23, 32.2) -> (-47.2007, 66.8082)
  line L5 (-20.5595, 32.2) -> (-23, 32.2)
  line L6 (-45.5533, 67.9422) -> (-20.5595, 32.2)
  line L7 (20.5595, 32.2) -> (45.5533, 67.9422)
  line L8 (23, 32.2) -> (20.5595, 32.2)
  line L9 (47.2007, 66.8082) -> (23, 32.2)
  line L10 (46.9289, 69.9094) -> (45.5533, 67.9422)
  line L11 (-46.9289, 69.9094) -> (-45.5533, 67.9422)
  line L12 (-20.5595, 32.2) -> (20.5595, 32.2)
  line L13 (61.2555, 90.3971) -> (46.9289, 69.9094)
  line L14 (-61.2555, 90.3971) -> (-46.9289, 69.9094)
  line L15 (61.2555, 90.3971) -> (-61.2555, 90.3971)
  line L16 (39.2054, 43.243) -> (37.7029, 45.8454)
  line L17 (42.598, 43.0192) -> (39.593, 43.0192)
  line L18 (44.4881, 45.8454) -> (42.9856, 43.243)
  line L19 (42.9856, 48.8954) -> (44.4881, 46.293)
  line L20 (39.593, 49.1192) -> (42.598, 49.1192)
  line L21 (37.7029, 46.293) -> (39.2054, 48.8954)
  line L22 (-42.9856, 43.243) -> (-44.4881, 45.8454)
  line L23 (-39.593, 43.0192) -> (-42.598, 43.0192)
  line L24 (-37.7029, 45.8454) -> (-39.2054, 43.243)
  line L25 (-39.2054, 48.8954) -> (-37.7029, 46.293)
  line L26 (-42.598, 49.1192) -> (-39.593, 49.1192)
  line L27 (-44.4881, 46.293) -> (-42.9856, 48.8954)
  line L28 (-32.0326, 24.1771) -> (-20.5595, 32.2)
  line L29 (-56.494, 59.158) -> (-32.0326, 24.1771)
  line L30 (-29.1792, -76.0975) -> (-28.5754, -79.5217)
  line L31 (32.0326, 24.1771) -> (20.5595, 32.2)
  line L32 (56.494, 59.158) -> (32.0326, 24.1771)
  line L33 (-29.9937, -78.6767) -> (-30.4818, -75.9085)
  arc A1 centre (0, 0) radius 81.8 clockwise from (47.2007, 66.8082) to (-30.4818, -75.9085)
  arc A2 centre (0, 0) radius 84.2 clockwise from (-47.6146, -69.4441) to (-29.9937, -78.6767)
  arc A3 centre (0, 0) radius 81.8 clockwise from (-49.9034, -64.8143) to (-47.2007, 66.8082)
  arc A4 centre (0, 0) radius 81.8 clockwise from (-45.5533, 67.9422) to (45.5533, 67.9422)
  arc A5 centre (41.0955, 46.0692) radius 3.4 clockwise from (39.593, 43.0192) to (39.2054, 43.243)
  arc A6 centre (41.0955, 46.0692) radius 3.4 clockwise from (42.9856, 43.243) to (42.598, 43.0192)
  arc A7 centre (41.0955, 46.0692) radius 3.4 clockwise from (44.4881, 46.293) to (44.4881, 45.8454)
  arc A8 centre (41.0955, 46.0692) radius 3.4 clockwise from (42.598, 49.1192) to (42.9856, 48.8954)
  arc A9 centre (41.0955, 46.0692) radius 3.4 clockwise from (39.2054, 48.8954) to (39.593, 49.1192)
  arc A10 centre (41.0955, 46.0692) radius 3.4 clockwise from (37.7029, 45.8454) to (37.7029, 46.293)
  arc A11 centre (-41.0955, 46.0692) radius 3.4 clockwise from (-42.598, 43.0192) to (-42.9856, 43.243)
  arc A12 centre (-41.0955, 46.0692) radius 3.4 clockwise from (-39.2054, 43.243) to (-39.593, 43.0192)
  arc A13 centre (-41.0955, 46.0692) radius 3.4 clockwise from (-37.7029, 46.293) to (-37.7029, 45.8454)
  arc A14 centre (-41.0955, 46.0692) radius 3.4 clockwise from (-39.593, 49.1192) to (-39.2054, 48.8954)
  arc A15 centre (-41.0955, 46.0692) radius 3.4 clockwise from (-42.9856, 48.8954) to (-42.598, 49.1192)
  arc A16 centre (-41.0955, 46.0692) radius 3.4 clockwise from (-44.4881, 45.8454) to (-44.4881, 46.293)
  circle C1 centre (-41.0955, 46.0692) radius 1.7
  circle C2 centre (41.0955, 46.0692) radius 1.7
  point P14 (45.5533, 67.9422)
  point P17 (45.5533, 67.9422)
  point P18 (46.9289, 69.9094)
  point P13 (-45.5533, 67.9422)
  point P19 (-45.5533, 67.9422)
  point P20 (-46.9289, 69.9094)
  point P15 (20.5595, 32.2)
  point P21 (20.5595, 32.2)
  point P12 (-20.5595, 32.2)
  point P22 (-20.5595, 32.2)
  point P54 (-56.494, 59.158)
  point P58 (56.494, 59.158)
  point P23 (61.2555, 90.3971)
  point P24 (-61.2555, 90.3971)
  point P53 (-32.0326, 24.1771)
  point P57 (32.0326, 24.1771)
  coincident P14 P17
  coincident A2 P18
  parallel L7 L10
  coincident P13 P19
  coincident A2 P20
  parallel L6 L11
  coincident P15 P21
  coincident P12 P22
  parallel L10 L13
  parallel L11 L14
  concentric A11 C1
  concentric A5 C2
  perpendicular L4 L28
  coincident A3 P54
  perpendicular L28 L29
  perpendicular L7 L31
  coincident A1 P58
  perpendicular L31 L32
  dimension "d415" distance P18 P23 = 25
  dimension "d416" distance P20 P24 = 25
  dimension "d418" diameter C1 = 3.4
  dimension "d419" diameter C2 = 3.4
  dimension "d425" distance P22 P53 = 14
  dimension "d434" distance P21 P57 = 14
extrude "Extrude81" cut sketch "Sketch52" profile of C1 C2 along normal blind 6.65 and against normal blind 57
chamfer "Chamfer7" distance 1.5
extrude "Extrude80" cut sketch "Sketch52" profile of A2 L6 A4 L7 L10 L11 L12 L13 L14 L15 along normal blind 6.65 and against normal blind 54.7
combine "Combine5"
offset_faces "OffsetFaces25" distance -0.2
extrude "Extrude82" add sketch "Sketch52" profile of A1 A2 L1 L2 L3 A3 L4 L5 L6 L7 L8 L9 L10 L11 L16 A5 L17 A6 L18 A7 L19 A8 L20 A9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 along normal blind 6.65
sketch "Sketch53" plane through (0, 0, 34.75) normal (0, 0, -1) x axis (1, 0, 0)
  line L1 (29.1792, -76.0975) -> (28.5754, -79.5217)
  line L2 (-42.3208, 59.4806) -> (-47.192, 66.4467)
  line L3 (49.483, -67.1984) -> (49.9808, -64.3752)
  line L4 (32.0326, 24.1771) -> (20.5595, 32.2)
  line L5 (51.3849, 51.8516) -> (32.0326, 24.1771)
  line L6 (47.192, 66.4467) -> (42.3208, 59.4806)
  line L7 (22.3624, 30.9393) -> (42.3208, 59.4806)
  line L8 (-32.0326, 24.1771) -> (-51.3849, 51.8516)
  line L9 (-20.5595, 32.2) -> (-32.0326, 24.1771)
  line L10 (-47.1008, 70.1553) -> (-20.5595, 32.2)
  line L11 (47.5418, -69.8572) -> (48.055, -66.9466)
  line L12 (20.5595, 32.2) -> (47.1008, 70.1553)
  line L13 (48.055, -66.9466) -> (49.483, -67.1984)
  line L14 (-22.3624, 30.9393) -> (-42.3208, 59.4806)
  circle C1 centre (-41.0955, 46.0692) radius 1.7
  arc A1 centre (0, 0) radius 81.5 clockwise from (29.1792, -76.0975) to (-47.192, 66.4467)
  arc A2 centre (0, 0) radius 73 clockwise from (-51.3849, 51.8516) to (-42.3208, 59.4806)
  circle C2 centre (41.0955, 46.0692) radius 1.7
  arc A3 centre (0, 0) radius 73 clockwise from (42.3208, 59.4806) to (51.3849, 51.8516)
  arc A4 centre (0, 0) radius 81.5 clockwise from (47.192, 66.4467) to (49.9808, -64.3752)
  arc A5 centre (0, 0) radius 84.5 clockwise from (28.5754, -79.5217) to (-47.1008, 70.1553)
  arc A6 centre (0, 0) radius 84.5 clockwise from (47.1008, 70.1553) to (47.5418, -69.8572)
  point P18 (42.3208, 59.4806)
  point P20 (42.3208, 59.4806)
  point P21 (22.3624, 30.9393)
  point P9 (-42.3208, 59.4806)
  point P27 (-42.3208, 59.4806)
  point P28 (-22.3624, 30.9393)
  coincident P18 P20
  coincident L4 P21
  perpendicular L4 L7
  coincident P9 P27
  coincident L9 P28
  perpendicular L9 L14
extrude "Extrude83" add sketch "Sketch53" profile of C1 A2 C2 L4 L5 A3 L7 L8 L9 L14 along normal blind 2
sketch "Sketch55" plane through (0, 0, 41.4) normal (0, 0, 1) x axis (-1, 0, 0)
  line L1 (14, 32.2) -> (20.5595, 32.2)
  line L2 (14, 17.8152) -> (14, 32.2)
  line L3 (-14, 17.8152) -> (14, 17.8152)
  line L4 (-14, 32.2) -> (-14, 17.8152)
  line L5 (-20.5595, 32.2) -> (-14, 32.2)
  line L6 (-48.2472, 71.7946) -> (-20.5595, 32.2)
  line L7 (20.5595, 32.2) -> (48.2472, 71.7946)
  line L8 (-56.2173, -19.7921) -> (-55.4687, -24.0376)
  line L9 (-55.542, -18.5396) -> (-56.0995, -19.2923)
  line L10 (-53.8324, -18.0571) -> (-55.1325, -18.2863)
  line L11 (-52.1069, -24.0993) -> (-53.0794, -18.5843)
  line L12 (-53.9343, -25.0815) -> (-52.6342, -24.8523)
  line L13 (-55.1871, -24.4669) -> (-54.4057, -24.9836)
  line L14 (-58.5616, -6.4972) -> (-57.813, -10.7427)
  line L15 (-57.8862, -5.2447) -> (-58.4438, -5.9974)
  line L16 (-56.1766, -4.7622) -> (-57.4768, -4.9914)
  line L17 (-54.4512, -10.8044) -> (-55.4236, -5.2894)
  line L18 (-56.2786, -11.7866) -> (-54.9784, -11.5574)
  line L19 (-57.5313, -11.172) -> (-56.75, -11.6887)
  line L20 (-59.5395, 10.912) -> (-60.091, 10.8147)
  line L21 (-56.7009, 3.4516) -> (-57.8018, 9.6952)
  line L22 (-58.4691, 1.6166) -> (-57.9176, 1.7139)
  line L23 (-61.3077, 9.0771) -> (-60.2068, 2.8334)
  line L24 (-23, 13.8152) -> (-23, -61.1848)
  line L25 (23, 13.8152) -> (-23, 13.8152)
  line L26 (23, -61.1848) -> (23, 13.8152)
  line L27 (-23, -61.1848) -> (23, -61.1848)
  line L28 (-47.0259, -36.2146) -> (-47.4127, -34.0213)
  arc A1 centre (0, 0) radius 86.5 clockwise from (48.2472, 71.7946) to (-48.2472, 71.7946)
  circle C1 centre (41.0955, 46.0692) radius 1.7
  circle C2 centre (-41.0955, 46.0692) radius 1.7
  arc A2 centre (-55.5772, -19.6792) radius 0.65 clockwise from (-56.2173, -19.7921) to (-56.0995, -19.2923)
  arc A3 centre (-55.0196, -18.9265) radius 0.65 clockwise from (-55.542, -18.5396) to (-55.1325, -18.2863)
  arc A4 centre (-53.7195, -18.6972) radius 0.65 clockwise from (-53.8324, -18.0571) to (-53.0794, -18.5843)
  arc A5 centre (-52.7471, -24.2121) radius 0.65 clockwise from (-52.1069, -24.0993) to (-52.6342, -24.8523)
  arc A6 centre (-54.0472, -24.4414) radius 0.65 clockwise from (-53.9343, -25.0815) to (-54.4057, -24.9836)
  arc A7 centre (-54.8286, -23.9247) radius 0.65 clockwise from (-55.1871, -24.4669) to (-55.4687, -24.0376)
  arc A8 centre (-57.1728, -10.6298) radius 0.65 clockwise from (-57.5313, -11.172) to (-57.813, -10.7427)
  arc A9 centre (-57.9214, -6.3843) radius 0.65 clockwise from (-58.5616, -6.4972) to (-58.4438, -5.9974)
  arc A10 centre (-57.3639, -5.6316) radius 0.65 clockwise from (-57.8862, -5.2447) to (-57.4768, -4.9914)
  arc A11 centre (-56.0637, -5.4023) radius 0.65 clockwise from (-56.1766, -4.7622) to (-55.4236, -5.2894)
  arc A12 centre (-55.0913, -10.9172) radius 0.65 clockwise from (-54.4512, -10.8044) to (-54.9784, -11.5574)
  arc A13 centre (-56.3915, -11.1465) radius 0.65 clockwise from (-56.2786, -11.7866) to (-56.75, -11.6887)
  arc A14 centre (-59.8305, 9.3375) radius 1.5 clockwise from (-61.3077, 9.0771) to (-60.091, 10.8147)
  arc A15 centre (-59.279, 9.4348) radius 1.5 clockwise from (-59.5395, 10.912) to (-57.8018, 9.6952)
  arc A16 centre (-58.1781, 3.1911) radius 1.5 clockwise from (-56.7009, 3.4516) to (-57.9176, 1.7139)
  arc A17 centre (-58.7296, 3.0938) radius 1.5 clockwise from (-58.4691, 1.6166) to (-60.2068, 2.8334)
  circle C3 centre (47, -60.7321) radius 1.7
  circle C4 centre (-57.0248, -52.0589) radius 1.7
  circle C5 centre (76.0955, -10.3372) radius 1.7
  circle C6 centre (-76.0955, -10.3372) radius 1.7
  arc A18 centre (-50.1737, -35.6389) radius 3.2 clockwise from (-47.0259, -36.2146) to (-47.4127, -34.0213)
  circle C7 centre (47, -60.7321) radius 3
  circle C8 centre (76.0955, -10.3372) radius 3
  circle C9 centre (41.0955, 46.0692) radius 3
  circle C10 centre (-76.0955, -10.3372) radius 3
  circle C11 centre (-41.0955, 46.0692) radius 3
  circle C12 centre (-57.0248, -52.0589) radius 3
  concentric C3 C7
  concentric C5 C8
  concentric C1 C9
  concentric C4 C12
  dimension "d435" diameter C7 = 6
  dimension "d436" diameter C8 = 6
  dimension "d437" diameter C9 = 6
  dimension "d438" diameter C12 = 6
extrude "Extrude85" cut sketch "Sketch55" profile of C1 C2 C3 C4 C5 C6 C7 C8 C9 C10 C11 C12 against normal blind 5
chamfer "Chamfer8" distance 1.3
fillet "Fillet6" radius 2.5
sketch "Sketch54" plane through (0, -32.2, 0) normal (0, -1, 0) x axis (1, 0, 0)
  line L1 (-23, 4.6416) -> (23, 4.6416)
  line L2 (-23, -17.25) -> (-23, 4.6416)
  line L3 (-11.5, -17.25) -> (-23, -17.25)
  line L4 (-11.5, -20.25) -> (-11.5, -17.25)
  line L5 (11.5, -20.25) -> (-11.5, -20.25)
  line L6 (11.5, -17.25) -> (11.5, -20.25)
  line L7 (23, -17.25) -> (11.5, -17.25)
  line L8 (23, 4.6416) -> (23, -17.25)
  circle C1 centre (0, -7.75) radius 2.415
  circle C2 centre (0, -7.75) radius 5
  concentric C1 C2
  dimension "d431" diameter C2 = 10
extrude "Extrude84" cut sketch "Sketch54" profile of C1 C2 against normal blind 30
sketch "Sketch56" plane through (0, 0, 39.3) normal (0, 0, -1) x axis (1, 0, 0)
  line L1 (30.5256, -68.4617) -> (30.9386, -66.1196)
  line L2 (47.2673, -71.4137) -> (30.5256, -68.4617)
  line L3 (48.055, -66.9466) -> (47.2673, -71.4137)
  line L4 (49.483, -67.1984) -> (48.055, -66.9466)
  line L5 (52.3633, -50.8634) -> (49.483, -67.1984)
  line L6 (47.2673, -71.4137) -> (47.0623, -72.5768)
  line L7 (30.5256, -68.4617) -> (47.2673, -71.4137)
  line L8 (28.1769, -81.7821) -> (30.5256, -68.4617)
  line L9 (29.9937, -78.6767) -> (30.4818, -75.9085)
  line L10 (29.5306, -81.3031) -> (29.9937, -78.6767)
  line L11 (32.3255, -65.4528) -> (30.4818, -75.9085)
  line L12 (-22.3624, 30.9393) -> (-45.7258, 64.35)
  line L13 (-20.5595, 32.2) -> (-22.3624, 30.9393)
  line L14 (-47.1008, 70.1553) -> (-20.5595, 32.2)
  line L15 (29.1792, -76.0975) -> (28.5754, -79.5217)
  line L16 (31.5136, -67.1777) -> (31.4615, -67.4732)
  line L17 (31.5136, -67.1777) -> (31.2181, -67.1256)
  line L18 (31.166, -67.4211) -> (31.2181, -67.1256)
  line L19 (31.4615, -67.4732) -> (31.166, -67.4211)
  line L20 (30.9688, -68.5399) -> (31.166, -67.4211)
  line L21 (31.4371, -65.8841) -> (31.2181, -67.1256)
  line L22 (30.7718, -68.5051) -> (30.9688, -68.5399)
  line L23 (31.2154, -65.9894) -> (30.7718, -68.5051)
  arc A1 centre (0, 0) radius 73 clockwise from (52.3633, -50.8634) to (30.9386, -66.1196)
  arc A2 centre (0, 0) radius 86.5 clockwise from (47.0623, -72.5768) to (28.1769, -81.7821)
  arc A3 centre (0, 0) radius 84.5 clockwise from (28.5754, -79.5217) to (-47.1008, 70.1553)
  arc A4 centre (0, 0) radius 81.5 clockwise from (29.1792, -76.0975) to (-49.2865, 64.9084)
  arc A5 centre (-47.7746, 62.9173) radius 2.5 clockwise from (-49.2865, 64.9084) to (-45.7258, 64.35)
  circle C1 centre (0, 0) radius 84.5
  circle C2 centre (0, 0) radius 81.5
  point P15 (29.9937, -78.6767)
  point P16 (29.9937, -78.6767)
  point P17 (29.5306, -81.3031)
  point P14 (30.4818, -75.9085)
  point P18 (30.4818, -75.9085)
  point P19 (32.3255, -65.4528)
  point P24 (28.5754, -79.5217)
  point P26 (29.1792, -76.0975)
  point P34 (31.166, -67.4211)
  point P35 (31.166, -67.4211)
  point P36 (30.9688, -68.5399)
  point P33 (31.2181, -67.1256)
  point P37 (31.2181, -67.1256)
  point P38 (31.4371, -65.8841)
  point P40 (31.2154, -65.9894)
  point P39 (30.7718, -68.5051)
  coincident P15 P16
  coincident A2 P17
  parallel L9 L10
  coincident P14 P18
  coincident A1 P19
  perpendicular L7 L11
  concentric A3 C1
  coincident P24 C1
  concentric A3 C2
  coincident P26 C2
  coincident P34 P35
  coincident L7 P36
  perpendicular L7 L20
  coincident P33 P37
  coincident A1 P38
  perpendicular L17 L21
  perpendicular L20 L22
  coincident A1 P40
  perpendicular L7 L23
  dimension "d448" distance P36 P39 = 0.2
extrude "Extrude86" add sketch "Sketch56" profile of A1 L1 L2 L7 L8 A2 L10 L11 C1 C2 L22 L23 along normal blind 6.55
extrude "Extrude87" add sketch "Sketch56" profile of A1 L2 L7 L8 L9 L10 L11 L15 C1 C2 L16 L17 L18 L19 L20 L21 L22 L23 along normal blind 4.55
extrude "Extrude88" cut of existing geometry blind -2.1
extrude "Extrude89" add of existing geometry blind 5
extrude "Extrude90" cut of existing geometry blind -5 second side blind 10.3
